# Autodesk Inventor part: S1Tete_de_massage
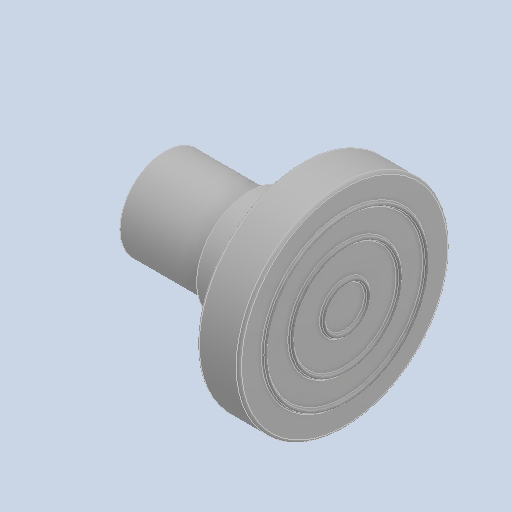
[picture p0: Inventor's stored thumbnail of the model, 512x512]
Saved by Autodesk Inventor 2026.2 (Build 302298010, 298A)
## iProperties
Created: 1601-01
Part Number: S1Tete_de_massage
Material: PA Type 6
Document SubType Name: Modeling
Designer: mel
Density: 1.12 g/cm^3
Appearance: light grey high gloss plastic
Author: mel
Sending System: SOLIDWORKS 2023
Part Number: Tete_de_massage
Last Saved Date: 2025-04-02
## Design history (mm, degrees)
feature "Congé2"
node "Solide1"
